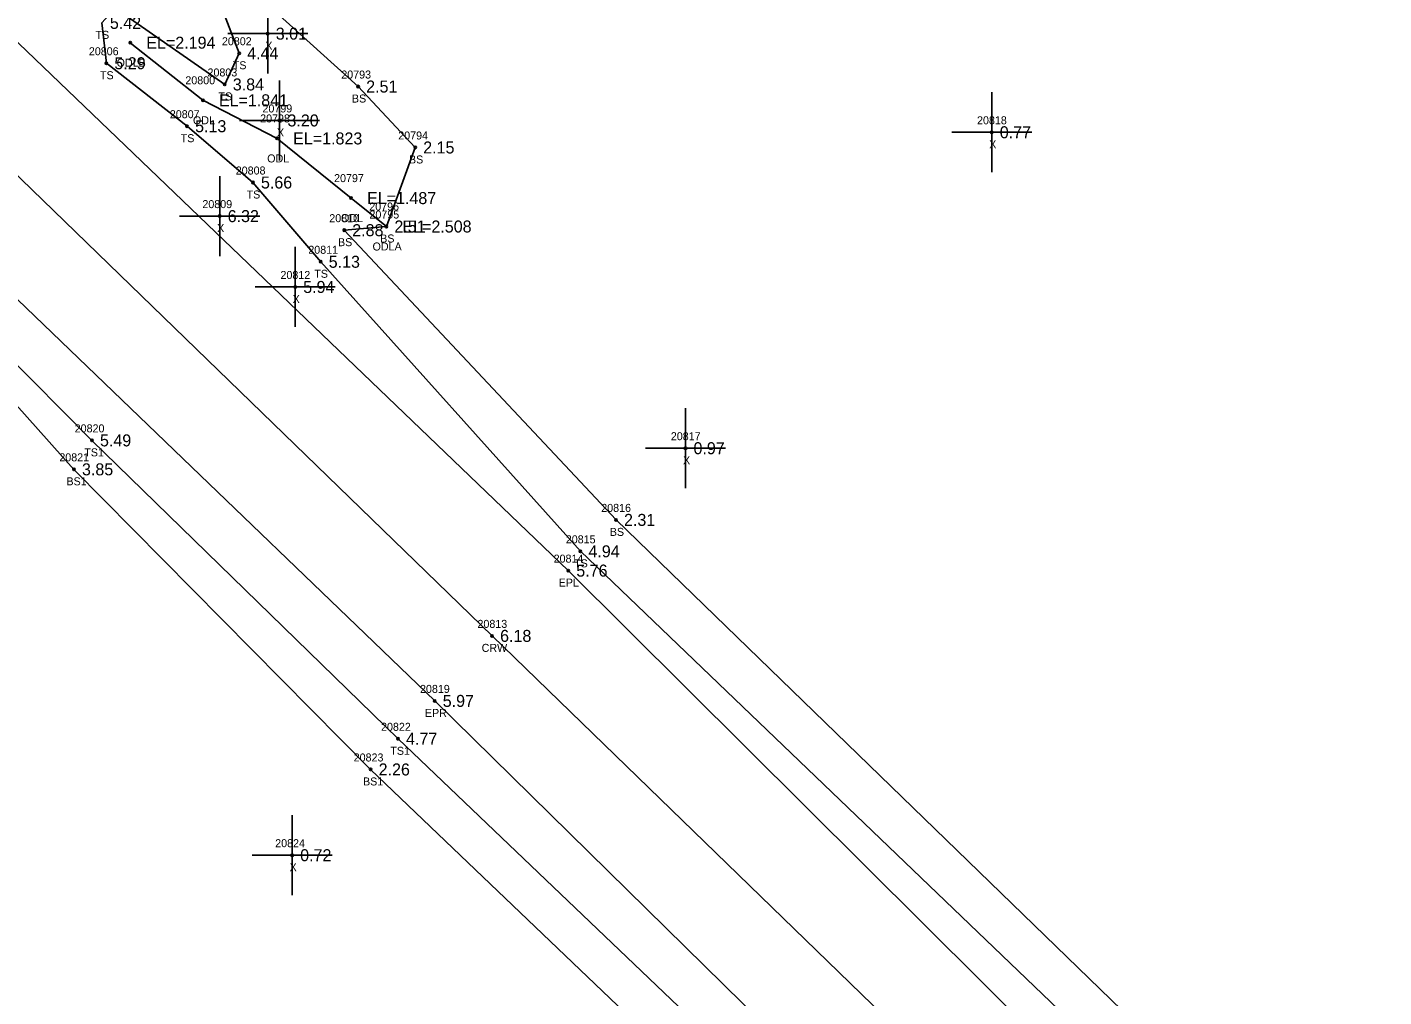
# Model space of a CAD drawing. Extents: x 2608745 to 2610333, y 641917 to 643463.
# Drawn here: x 2609277.1 to 2609446.6, y 642826.6 to 642947.8 of the extents above; entities that cross this region are included whole.
import ezdxf

# ---------------------------------------------------------------- set-up
doc = ezdxf.new("R2010")
doc.units = 0
for name, color, linetype in [('RD_DTM_BkLn1', 7, 'Continuous'), ('RD_DTM_BkLn2', 7, 'Continuous'), ('RD_DTM_BkLn_txCode', 7, 'Continuous'), ('RD_EX_H2O', 7, 'Continuous'), ('RD_EX_H2O_txCode', 7, 'Continuous'), ('RD_EX_Misc', 7, 'Continuous'), ('RD_EX_Misc_txCode', 7, 'Continuous'), ('RD_EX_Road', 7, 'Continuous'), ('RD_EX_Road_txCode', 7, 'Continuous'), ('RD_EX_TX_H2O_ELEV', 7, 'Continuous'), ('RD_EX_TX_Misc_ELEV', 7, 'Continuous'), ('RD_EX_TX_Road_ELEV', 7, 'Continuous'), ('RD_HC_Survey_ELEV', 7, 'Continuous'), ('RD_HC_Survey_txCode', 7, 'Continuous'), ('RD_SMD_Locator', 7, 'Continuous')]:
    doc.layers.add(name, color=color, linetype=linetype)

msp = doc.modelspace()

# ---------------------------------------------------------------- linework, layer by layer
at = {"layer": 'RD_DTM_BkLn1'}
msp.add_lwpolyline([(2608814.73, 643373.65), (2608890.45, 643300.26), (2608962.19, 643231.31), (2609034.91, 643161.19), (2609108.48, 643089.9), (2609179.19, 643022.29), (2609255.71, 642948.78), (2609335.19, 642871.73), (2609410.7, 642798.48), (2609491.67, 642719.95), (2609518.07, 642695.15)], dxfattribs=at)
at = {"layer": 'RD_DTM_BkLn2'}
for points in [[(2609298.5, 642957.84), (2609303.58, 642944.57), (2609301.78, 642940.67), (2609288.09, 642950.22), (2609286.42, 642948.37), (2609286.98, 642943.32), (2609297.07, 642935.45), (2609305.3, 642928.41), (2609313.77, 642918.5), (2609346.23, 642882.3), (2609422.21, 642809.45), (2609480.56, 642755.4), (2609506.75, 642733.83), (2609516.79, 642724.84), (2609528.1, 642713.09), (2609531.25, 642709.73), (2609532.97, 642706.82)], [(2609299.18, 642957.88), (2609318.45, 642940.41), (2609325.58, 642932.79), (2609321.98, 642922.91), (2609316.71, 642922.45), (2609350.68, 642886.23), (2609426.26, 642812.92), (2609486.18, 642762.85), (2609511.6, 642739.79), (2609523.11, 642729.83), (2609533.96, 642717.19), (2609534.91, 642710.27), (2609532.97, 642706.82)], [(2609261.87, 642916.52), (2609266.58, 642914.91), (2609285.18, 642896.17), (2609323.43, 642858.86), (2609399.07, 642786.65), (2609450.77, 642732.34), (2609478.69, 642705.43), (2609489.94, 642696.01), (2609499.39, 642685.95), (2609506.29, 642680.17), (2609532.97, 642706.82)], [(2609260.59, 642912.35), (2609267.04, 642908.29), (2609268.14, 642909.06), (2609282.93, 642892.55), (2609320.01, 642855.03), (2609395.77, 642782.61), (2609444.33, 642725.24)]]:
    msp.add_lwpolyline(points, dxfattribs=at)
at = {"layer": 'RD_EX_H2O'}
msp.add_lwpolyline([(2609321.98, 642922.91), (2609317.56, 642926.46), (2609308.32, 642933.92), (2609299.04, 642938.69), (2609289.97, 642945.89)], dxfattribs=at)
at = {"layer": 'RD_EX_Misc'}
for p, q in [((2609307.15, 642942.02), (2609307.15, 642952.02)), ((2609302.15, 642947.02), (2609312.15, 642947.02)), ((2609308.61, 642931.17), (2609308.61, 642941.17)), ((2609397.64, 642929.69), (2609397.64, 642939.69)), ((2609303.61, 642936.17), (2609313.61, 642936.17)), ((2609392.64, 642934.69), (2609402.64, 642934.69)), ((2609301.14, 642919.21), (2609301.14, 642929.21)), ((2609296.14, 642924.21), (2609306.14, 642924.21)), ((2609310.58, 642910.35), (2609310.58, 642920.35)), ((2609305.58, 642915.35), (2609315.58, 642915.35)), ((2609359.36, 642890.19), (2609359.36, 642900.19)), ((2609354.36, 642895.19), (2609364.36, 642895.19)), ((2609310.2, 642839.31), (2609310.2, 642849.31)), ((2609305.2, 642844.31), (2609315.2, 642844.31))]:
    msp.add_line(p, q, dxfattribs=at)
at = {"layer": 'RD_EX_Road'}
for points in [[(2608806.89, 643364.99), (2608810.18, 643361.1), (2608820.75, 643351.25), (2608881.81, 643292.24), (2608917.83, 643257.49), (2608933.21, 643242.71), (2608954.07, 643222.83), (2609026.06, 643154.19), (2609039.6, 643139.96), (2609073.88, 643106.95), (2609100.48, 643081.89), (2609124.19, 643058.87), (2609171.61, 643013.71), (2609183.19, 643002.28), (2609197.91, 642988.37), (2609247.59, 642940.95), (2609328.02, 642863.6), (2609402.61, 642790.3), (2609474.23, 642720.69), (2609483.84, 642711.58), (2609495.78, 642699.92), (2609509.81, 642686.45)], [(2609058.51, 643155.46), (2609096.06, 643119.37), (2609116.51, 643099.11), (2609162.4, 643055.35), (2609177.21, 643041.34), (2609188.35, 643030.96), (2609199.91, 643019.76), (2609205.8, 643014.04), (2609217.13, 643003.17), (2609235.83, 642983.9), (2609237.03, 642983.51), (2609256.8, 642965.04), (2609258.49, 642962.51), (2609263.65, 642957.66), (2609344.71, 642879.89), (2609418.83, 642806.19), (2609500.61, 642728.46), (2609512.38, 642716.82), (2609526.19, 642703.5)]]:
    msp.add_lwpolyline(points, dxfattribs=at)
at = {"layer": 'RD_SMD_Locator'}
for centre in [(2609289.97, 642945.89), (2609307.15, 642947.02), (2609303.58, 642944.57), (2609286.98, 642943.32), (2609301.78, 642940.67), (2609318.45, 642940.41), (2609299.04, 642938.69), (2609308.61, 642936.17), (2609297.07, 642935.45), (2609308.32, 642933.92), (2609397.64, 642934.69), (2609325.58, 642932.79), (2609305.3, 642928.41), (2609317.56, 642926.46), (2609301.14, 642924.21), (2609316.71, 642922.45), (2609321.98, 642922.91), (2609321.98, 642922.91), (2609313.77, 642918.5), (2609310.58, 642915.35), (2609285.18, 642896.17), (2609359.36, 642895.19), (2609282.93, 642892.55), (2609350.68, 642886.23), (2609346.23, 642882.3), (2609344.71, 642879.89), (2609335.19, 642871.73), (2609328.02, 642863.6), (2609323.43, 642858.86), (2609320.01, 642855.03), (2609310.2, 642844.31)]:
    msp.add_circle(centre, 0.15, dxfattribs=at)

# ---------------------------------------------------------------- texts
at = {"layer": 'RD_DTM_BkLn_txCode'}
for s, p in [('TS', (2609285.62, 642946.37)), ('20802', (2609301.42, 642945.57)), ('20806', (2609284.79, 642944.32)), ('20803', (2609299.62, 642941.67)), ('TS', (2609302.78, 642942.57)), ('20793', (2609316.34, 642941.41)), ('TS', (2609286.18, 642941.32)), ('TS', (2609300.99, 642938.67)), ('BS', (2609317.67, 642938.41)), ('20807', (2609294.91, 642936.45)), ('TS', (2609296.27, 642933.45)), ('20794', (2609323.46, 642933.79)), ('BS', (2609324.8, 642930.79)), ('20808', (2609303.15, 642929.41)), ('TS', (2609304.51, 642926.41)), ('20810', (2609314.84, 642923.45)), ('20795', (2609319.86, 642923.91)), ('20811', (2609312.22, 642919.5)), ('BS', (2609315.93, 642920.45)), ('BS', (2609321.2, 642920.91)), ('TS', (2609312.97, 642916.5)), ('20820', (2609283.02, 642897.17)), ('TS1', (2609284.22, 642894.17)), ('20821', (2609281.1, 642893.55)), ('BS1', (2609281.99, 642890.55)), ('20816', (2609348.83, 642887.23)), ('BS', (2609349.9, 642884.23)), ('20815', (2609344.4, 642883.3)), ('TS', (2609345.44, 642880.3)), ('20822', (2609321.31, 642859.86)), ('TS1', (2609322.47, 642856.86)), ('20823', (2609317.89, 642856.03)), ('BS1', (2609319.06, 642853.03))]:
    msp.add_text(s, height=1, dxfattribs=at).set_placement(p)
at = {"layer": 'RD_EX_H2O_txCode'}
for s, p in [('ODLB', (2609288.26, 642942.89)), ('20800', (2609296.85, 642940.69)), ('ODL', (2609297.8, 642935.69)), ('20798', (2609306.2, 642935.92)), ('ODL', (2609307.08, 642930.92)), ('20797', (2609315.44, 642928.46)), ('20796', (2609319.84, 642924.91)), ('ODL', (2609316.31, 642923.46)), ('ODLA', (2609320.25, 642919.91))]:
    msp.add_text(s, height=1, dxfattribs=at).set_placement(p)
at = {"layer": 'RD_EX_Misc_txCode'}
for s, p in [('X', (2609306.84, 642945.02)), ('20799', (2609306.49, 642937.17)), ('20818', (2609395.8, 642935.69)), ('X', (2609308.3, 642934.17)), ('X', (2609397.32, 642932.69)), ('20809', (2609298.98, 642925.21)), ('X', (2609300.82, 642922.21)), ('20812', (2609308.74, 642916.35)), ('X', (2609310.26, 642913.35)), ('20817', (2609357.53, 642896.19)), ('X', (2609359.05, 642893.19)), ('20824', (2609308.08, 642845.31)), ('X', (2609309.88, 642842.31))]:
    msp.add_text(s, height=1, dxfattribs=at).set_placement(p)
at = {"layer": 'RD_EX_Road_txCode'}
for s, p in [('20814', (2609342.88, 642880.89)), ('EPL', (2609343.51, 642877.89)), ('20819', (2609326.18, 642864.6)), ('EPR', (2609326.79, 642861.6))]:
    msp.add_text(s, height=1, dxfattribs=at).set_placement(p)
at = {"layer": 'RD_EX_TX_H2O_ELEV'}
for s, p in [('EL=2.194', (2609291.97, 642945.14)), ('EL=1.841', (2609301.04, 642937.94)), ('EL=1.823', (2609310.32, 642933.17)), ('EL=1.487', (2609319.56, 642925.71)), ('EL=2.508', (2609323.98, 642922.16))]:
    msp.add_text(s, height=1.5, dxfattribs=at).set_placement(p)
at = {"layer": 'RD_EX_TX_Misc_ELEV'}
for s, p in [('5.42', (2609287.42, 642947.62)), ('3.01', (2609308.15, 642946.27)), ('5.29', (2609287.98, 642942.57)), ('4.44', (2609304.58, 642943.82)), ('3.84', (2609302.78, 642939.92)), ('2.51', (2609319.45, 642939.66)), ('5.13', (2609298.07, 642934.7)), ('3.20', (2609309.61, 642935.42)), ('0.77', (2609398.64, 642933.94)), ('2.15', (2609326.58, 642932.04)), ('5.66', (2609306.3, 642927.66)), ('6.32', (2609302.14, 642923.46)), ('2.88', (2609317.71, 642921.7)), ('2.51', (2609322.98, 642922.16)), ('5.13', (2609314.77, 642917.75)), ('5.94', (2609311.58, 642914.6)), ('5.49', (2609286.18, 642895.42)), ('0.97', (2609360.36, 642894.44)), ('3.85', (2609283.93, 642891.8)), ('2.31', (2609351.68, 642885.48)), ('4.94', (2609347.23, 642881.55)), ('4.77', (2609324.43, 642858.11)), ('2.26', (2609321.01, 642854.28)), ('0.72', (2609311.2, 642843.56))]:
    msp.add_text(s, height=1.5, dxfattribs=at).set_placement(p)
at = {"layer": 'RD_EX_TX_Road_ELEV'}
for s, p in [('5.76', (2609345.71, 642879.14)), ('5.97', (2609329.02, 642862.85))]:
    msp.add_text(s, height=1.5, dxfattribs=at).set_placement(p)
at = {"layer": 'RD_HC_Survey_ELEV'}
msp.add_text('6.18', height=1.5, dxfattribs=at).set_placement((2609336.19, 642870.98))
at = {"layer": 'RD_HC_Survey_txCode'}
for s, p in [('20813', (2609333.36, 642872.73)), ('CRW', (2609333.88, 642869.73))]:
    msp.add_text(s, height=1, dxfattribs=at).set_placement(p)

doc.saveas('drawing.dxf')
